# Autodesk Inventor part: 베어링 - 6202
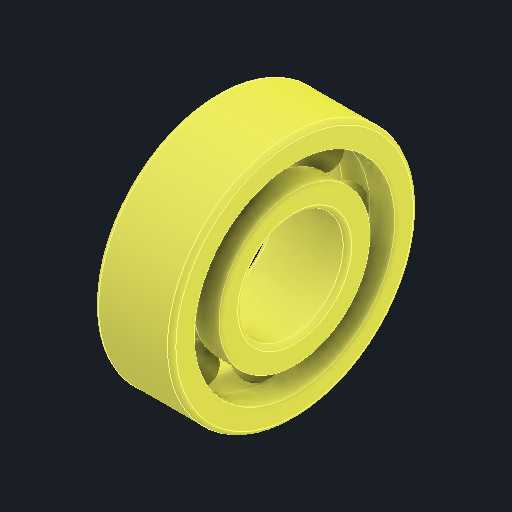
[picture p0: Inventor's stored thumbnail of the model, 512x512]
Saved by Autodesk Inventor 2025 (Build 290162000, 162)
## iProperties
Created: 2025-08
Part Number: 베어링 - 6202
Material: 강, 연강
Description: 깊은 그루브 볼 베어링
Document SubType Name: Modeling
Designer: infra005
Density: 7.86 g/cm^3
Appearance: 기본값
Author: jhkim
Sending System: Autodesk Inventor 2026
Preprocessor: ST-DEVELOPER v20.1
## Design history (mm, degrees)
feature "Solid1"
feature "Solid1:1"
feature "Solid1:2"
feature "Solid1:3"
feature "Solid1:4"
feature "Solid1:5"
feature "Solid1:6"
feature "Solid1:7"
feature "Solid1:8"
feature "Solid1:9"
node "솔리드1"
node "솔리드2"
node "솔리드3"
node "솔리드4"
node "솔리드5"
node "솔리드6"
node "솔리드7"
node "솔리드8"
node "솔리드9"
node "솔리드10"
